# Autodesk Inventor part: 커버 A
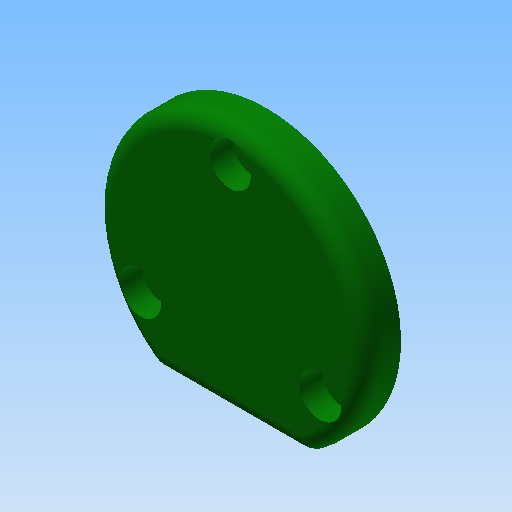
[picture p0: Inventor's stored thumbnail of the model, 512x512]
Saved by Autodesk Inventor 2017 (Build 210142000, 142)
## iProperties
Created: 2020-04
Part Number: 커버 A
Material: 알루미늄 6061
Document SubType Name: Modeling
Designer: mduedu
Density: 2.71 g/cm^3
Mass: 30.8964 g
Surface Area: 61.0159 cm^2
Volume: 11.4009 cm^3
Appearance: 진녹색
Author: mduedu
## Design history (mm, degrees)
sketch "스케치1"
  geometry: C1 r 26 at (0, 0); 1 further point
  constraints: 1 centre point, 1 coincident
  dimensions: "d0" = 52 diameter of C1
extrude "돌출1" new body sketch "스케치1" distance "d1" = 7; taper "d2" = 0 deg
sketch "스케치2"
  geometry: L1 (-14.62, -21.5)-(14.62, -21.5); A1 r 26 centre (0, 0) between (-14.62, -21.5) and (14.62, -21.5) reference; 1 further point
  constraints: 2 end point, 2 point on circle, 1 horizontal
  dimensions: "d3" = 21.5 distance from line of L1 point (0, 0)
extrude "돌출2" cut sketch "스케치2" stored distance "d4" = 7; taper "d5" = 0 deg
fillet "모깎기1" dims "d6" = 3
fillet "모깎기2" dims "d7" = 3
sketch "스케치3" dims "d8" = 40
  geometry: 3 further points
  constraints: 2 vertical alignment, 1 coincident, 2 other
hole "구멍1" sketch "스케치3" at (0, 20) diameter "d9" = 4.5; stored, may be unused: countersink angle "d13" = 90 deg, drill point angle "d15" = 118 deg; dims "d10" = 6, "d11" = 8, "d12" = 4.4, "d14" = 8
sketch "스케치4"
  geometry: C1 r 16 at (0, 0); 1 further point
  constraints: 1 centre point, 1 coincident
  dimensions: "d19" = 32 diameter of C1
extrude "돌출3" join sketch "스케치4" distance "d20" = 3; taper "d21" = 0 deg
sketch "스케치5"
  geometry: C1 r 14 at (0, 0); 1 further point
  constraints: 1 centre point, 1 coincident
  dimensions: "d22" = 28 diameter of C1
extrude "돌출4" cut sketch "스케치5" distance "d23" = 7; taper "d24" = 0 deg
fillet "모깎기3" dims "d25" = 3
chamfer "모따기1" distance "d26" = 0.5; stored, may be unused: second distance "d27" = 2, angle "d28" = 45 deg
node "솔리드1"
pattern_circular "원형 패턴1" dims angle "d17" = 360 deg
node "투영된 루프1"
